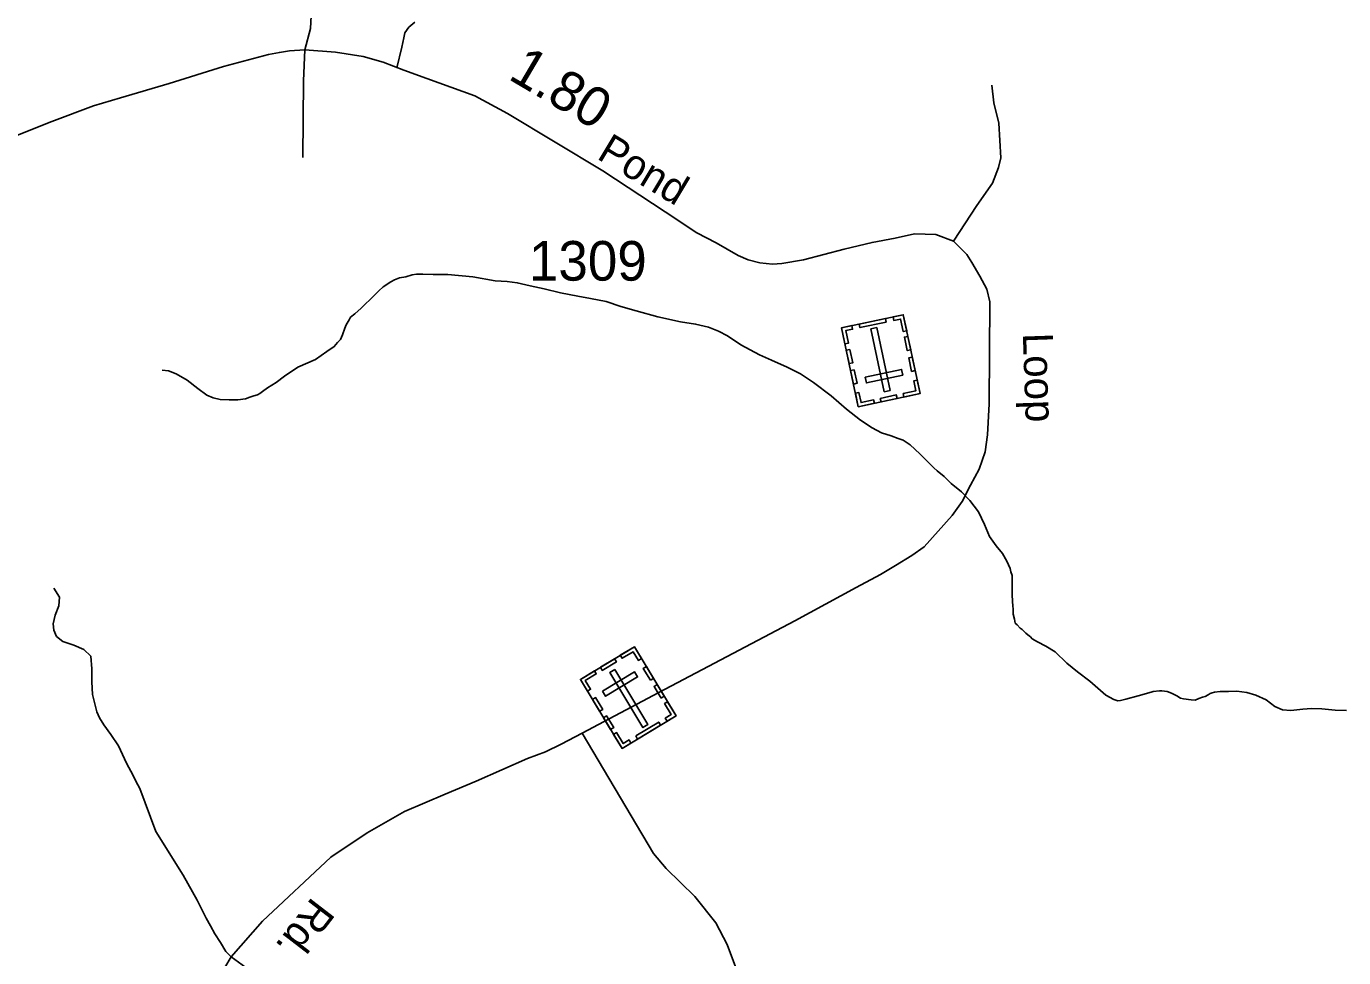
# Model space of a CAD drawing. Extents: x 2220236 to 2384410, y 720751 to 894131.
# Drawn here: x 2271918 to 2276076, y 823189 to 826128 of the extents above; entities that cross this region are included whole.
import ezdxf

# ---------------------------------------------------------------- set-up
doc = ezdxf.new("R2010")
doc.units = 0
doc.layers.add('Default', color=7, linetype='Continuous')

msp = doc.modelspace()

# ---------------------------------------------------------------- linework, layer by layer
at = {"layer": 'Default'}
for points in [[(2272668.9, 827422.7), (2272667.4, 827378.7), (2272658, 827302.7), (2272646.7, 827034.6), (2272645.9, 826910.7), (2272648.2, 826868.6), (2272658.5, 826824.8), (2272672.9, 826787), (2272695.4, 826743.3), (2272754.7, 826585.9), (2272783.6, 826504.1), (2272793.8, 826466.3), (2272804.4, 826416.3), (2272820.9, 826241.8), (2272815, 826121.7), (2272797.3, 826054.7)], [(2273144.6, 826141.4), (2273124.9, 826125.6), (2273113.1, 826107.9), (2273109.2, 826092.1), (2273103.3, 826062.6), (2273087.5, 825997.7)], [(2271512.3, 825634.5), (2271998.5, 825828.3), (2272130.4, 825877.6), (2272215, 825903.2), (2272369, 825948.5), (2272540.4, 826002.1), (2272682, 826039.3), (2272717.1, 826046.3), (2272749.1, 826050.8), (2272797.3, 826054.7), (2272893.9, 826047.3), (2272981.3, 826033.1), (2273044.2, 826015.4), (2273109.2, 825989.8), (2273182, 825964.2), (2273333.4, 825909.1), (2273436.7, 825853.9), (2273737.7, 825672.8), (2273934.1, 825543.3), (2274034.7, 825476.4), (2274094.9, 825445), (2274165.2, 825405.5), (2274196.2, 825391.3), (2274233.5, 825382.3), (2274272.9, 825377.5), (2274302.4, 825379.5), (2274371.3, 825391.3), (2274499.1, 825424.8), (2274587.7, 825446.4), (2274660.5, 825460.2), (2274721.5, 825474), (2274788.3, 825472), (2274844.6, 825450), (2274886.9, 825408.3), (2274902.5, 825383.4), (2274928, 825340.1), (2274949.7, 825298.8), (2274959.5, 825259.4), (2274957.3, 824937.3), (2274952.3, 824839.4), (2274944.6, 824785.3), (2274925.1, 824731.1), (2274897.8, 824680.9), (2274872.3, 824628.6), (2274840.8, 824584.4), (2274751.7, 824485.5), (2274712.6, 824458.2), (2274661.4, 824426.7), (2274614.6, 824398.2), (2274537, 824357.5), (2274344, 824251.7), (2273914.4, 824025.9), (2273672.7, 823898.1), (2273605.8, 823862.6), (2273556.6, 823839), (2273499.6, 823817.4), (2273338.2, 823746.5), (2273239.9, 823705.1), (2273112, 823650), (2272993.9, 823583.1), (2272879.7, 823506.3), (2272663.6, 823304.5), (2272564.9, 823191.5), (2272524.2, 823124.4)], [(2272797.3, 826054.7), (2272793.4, 825956.3), (2272790.4, 825714.2)], [(2274965.9, 825942.9), (2274972.3, 825887), (2274987.1, 825823.1), (2274994, 825713.2), (2274986.3, 825683.2), (2274967.4, 825633.4), (2274918.2, 825562.6), (2274844.6, 825450)], [(2274070.9, 825178.8), (2274030.7, 825188.8), (2273983, 825196.4), (2273910.8, 825211.6), (2273842.7, 825231.1), (2273794.8, 825244.5), (2273748.5, 825260.2), (2273698.5, 825269.5), (2273658.3, 825276.9), (2273604.1, 825286.9), (2273552.2, 825300.4), (2273508.1, 825309.5), (2273467.7, 825319.2), (2273435.9, 825323.1), (2273397.9, 825324.9), (2273327.7, 825337.8), (2273248.1, 825345.1), (2273201.9, 825345.4), (2273169.8, 825346.7), (2273149.7, 825346.4), (2273135.9, 825344.1), (2273115.8, 825338), (2273096, 825334.4), (2273080.2, 825328.2), (2273068.2, 825321.9), (2273044.3, 825306), (2273030.6, 825293.2), (2273006.4, 825269.1), (2272984.7, 825248.8), (2272975, 825239.2), (2272955.3, 825220.9), (2272941.3, 825210.4), (2272937.2, 825202.3), (2272927.3, 825186.1), (2272923.5, 825176.3), (2272915.8, 825154.5), (2272909.7, 825140.5), (2272899.9, 825130.2), (2272890.2, 825118), (2272866.2, 825102.1), (2272830.6, 825077.5), (2272775, 825053.1), (2272733.1, 825024.5), (2272707.1, 825004.7), (2272679.2, 824987.9), (2272663.5, 824976), (2272655.5, 824969.6), (2272647.6, 824965.6), (2272635.7, 824961.9), (2272623.5, 824957.9), (2272609.6, 824953.2), (2272585.9, 824949.8), (2272558, 824949.4), (2272529.8, 824950.9), (2272508, 824956.3), (2272487.5, 824964.9), (2272459.7, 824985.8), (2272425.5, 825012.1), (2272391.1, 825031.5), (2272367.1, 825041.2), (2272347.1, 825043.3)], [(2276084.9, 823968.8), (2276048.9, 823970.2), (2276007, 823974.3), (2275974.9, 823976), (2275947, 823973.9), (2275909.1, 823969.1), (2275883.3, 823971.3), (2275858.9, 823982.3), (2275831.1, 824002.6), (2275798.6, 824018), (2275770.6, 824026.1), (2275738.5, 824030.1), (2275712.6, 824029.6), (2275686.7, 824029.5), (2275668.6, 824027.2), (2275660.7, 824025.1), (2275654.7, 824022.6), (2275648.8, 824018.8), (2275638.8, 824013.1), (2275630.9, 824011), (2275619, 824006.9), (2275606.8, 824002.3), (2275595, 824002.5), (2275570.8, 824006.3), (2275561, 824008.1), (2275549, 824015.9), (2275532.8, 824023.5), (2275518.8, 824029.7), (2275502.4, 824031.7), (2275494.6, 824031.8), (2275474.5, 824029.6), (2275468.5, 824027.4), (2275427, 824015.2), (2275388.7, 824004.5), (2275371.2, 824000.6), (2275363, 824000.1), (2275351, 824004.3), (2275325, 824018), (2275274.8, 824061.6), (2275236.3, 824091.3), (2275202.1, 824118.9), (2275165.5, 824154.1), (2275135.7, 824172.1), (2275109.4, 824185.8), (2275093.2, 824195.9), (2275087.4, 824201.6), (2275079.3, 824207.7), (2275073.2, 824213.4), (2275061, 824225.1), (2275055.2, 824229.5), (2275045.2, 824239.6), (2275039.1, 824245.3), (2275037.1, 824257.8), (2275032.5, 824273.3), (2275032.5, 824291.3), (2275032.3, 824297.2), (2275030.1, 824333.4), (2275030, 824373.4), (2275029.6, 824387.5), (2275029.4, 824395.7), (2275025.4, 824407.3), (2275023.3, 824417.1), (2275013, 824441), (2274998.7, 824465.2), (2274978.9, 824488.6), (2274958.5, 824518.5), (2274942.3, 824556.6), (2274923.7, 824596.3), (2274895.6, 824632), (2274869.3, 824659.8), (2274837, 824685.7), (2274814.8, 824707.5), (2274792.6, 824725.3), (2274782.6, 824735.4), (2274738.6, 824778.9), (2274708, 824808.1), (2274685.7, 824822.6), (2274670.1, 824827.9), (2274647.9, 824835.6), (2274617.6, 824846), (2274587.8, 824861.4), (2274551.5, 824885.1), (2274507, 824920.5), (2274458.7, 824962.5), (2274402.5, 825004), (2274362, 825031.7), (2274319.8, 825053.3), (2274269.8, 825074.6), (2274231.8, 825091.8), (2274173.4, 825123.5), (2274131.3, 825151.3), (2274103.1, 825166.6), (2274070.9, 825178.8)], [(2272005.3, 824354.8), (2272023, 824327.2), (2272021.1, 824299.7), (2272009.2, 824270.1), (2272003.3, 824242.6), (2272005.3, 824222.9), (2272013.2, 824203.2), (2272032.9, 824187.5), (2272068.3, 824175.7), (2272099.7, 824161.9), (2272121.4, 824140.2), (2272125.3, 824100.8), (2272125.3, 824059.5), (2272127.3, 824020.1), (2272133.2, 823994.5), (2272141.1, 823965), (2272148.7, 823946.4), (2272162.7, 823923.7), (2272184.6, 823893.9), (2272209, 823857.2), (2272234.4, 823802.9), (2272255.4, 823764.4), (2272264.1, 823746), (2272276, 823722.6), (2272327.1, 823587.2), (2272412.6, 823449.2), (2272457.8, 823370.5), (2272485.4, 823313.4), (2272499.1, 823289.7), (2272512.9, 823264.2), (2272530.6, 823236.6), (2272548.3, 823209), (2272564.9, 823191.5)], [(2273672.7, 823898.1), (2273739.6, 823783.9), (2273898, 823518.1), (2273937.3, 823470.9), (2274027.8, 823382.3), (2274094.7, 823299.6), (2274130.1, 823230.7), (2274159.6, 823151.9), (2274187.2, 823081.1), (2274182.3, 823053.5), (2274164.6, 823022)], [(2274164.6, 823022), (2273845.4, 823069.6), (2273647.2, 823079.7), (2273589.3, 823081.3), (2273559.4, 823074.9), (2273517.4, 823068.6), (2273459.8, 823046), (2273390.3, 822991.5), (2273240.1, 822808), (2273220.3, 822789.8), (2273166.3, 822779.4), (2273136.3, 822779), (2273070.1, 822806.3), (2272975.6, 822865.5), (2272858.7, 822958.3), (2272768.2, 823037.6), (2272703.7, 823090.9), (2272564.9, 823191.5)]]:
    msp.add_lwpolyline(points, dxfattribs=at)
for points in [[(2274738.9, 824969.3), (2274544.1, 824927.9), (2274491.2, 825177), (2274686, 825218.3)], [(2274653.6, 825211.4), (2274656, 825200.2), (2274677.5, 825204.8), (2274685.9, 825165.2), (2274696.8, 825167.5), (2274686, 825218.3)], [(2274523.6, 825183.9), (2274526, 825172.6), (2274504.5, 825168.1), (2274512.9, 825128.5), (2274502, 825126.2), (2274491.2, 825177)], [(2274632.2, 825195.2), (2274549.2, 825177.6), (2274546.8, 825188.7), (2274629.8, 825206.3)], [(2274626.1, 824975.3), (2274644.4, 824979.2), (2274602.3, 825177.5), (2274584, 825173.6)], [(2274700.5, 825149.9), (2274709.5, 825107.6), (2274698.4, 825105.2), (2274689.4, 825147.6)], [(2274517.4, 825108.7), (2274526.4, 825066.3), (2274515.2, 825063.9), (2274506.2, 825106.3)], [(2274714.5, 825084.2), (2274723.5, 825041.8), (2274712.3, 825039.4), (2274703.4, 825081.8)], [(2274531, 825044.2), (2274540, 825001.8), (2274528.9, 824999.4), (2274519.9, 825041.8)], [(2274684.8, 825027.4), (2274680.9, 825045.6), (2274565.8, 825021.2), (2274569.6, 825002.9)], [(2274729.9, 825011.6), (2274718.8, 825009.3), (2274725.5, 824977.8), (2274685.8, 824969.4), (2274688.1, 824958.5), (2274738.9, 824969.3)], [(2274535, 824970.3), (2274546.1, 824972.7), (2274552.8, 824941.2), (2274592.5, 824949.6), (2274594.8, 824938.7), (2274544.1, 824927.9)], [(2274666.4, 824953.9), (2274615.7, 824943.1), (2274613.3, 824954.3), (2274664, 824965)], [(2273666.8, 824067.5), (2273837.3, 824170.3), (2273968.8, 823952.3), (2273798.3, 823849.4)], [(2273859.7, 824133.2), (2273850, 824127.3), (2273833.4, 824154.9), (2273798.7, 824134), (2273792.9, 824143.5), (2273837.4, 824170.3)], [(2273730.2, 824105.7), (2273774.6, 824132.5), (2273780.5, 824122.7), (2273736.1, 824095.9)], [(2273689.2, 824030.4), (2273698.9, 824036.2), (2273682.3, 824063.8), (2273717, 824084.7), (2273711.3, 824094.3), (2273666.8, 824067.5)], [(2273736.9, 824030.3), (2273746.6, 824014.3), (2273847.4, 824075.1), (2273837.7, 824091.1)], [(2273775.3, 824098.7), (2273759.3, 824089), (2273864.1, 823915.4), (2273880, 823925.1)], [(2273887.7, 824064.7), (2273865.3, 824101.8), (2273875.1, 824107.7), (2273897.5, 824070.6)], [(2273921.7, 824008.3), (2273899.4, 824045.4), (2273909.1, 824051.3), (2273931.5, 824014.2)], [(2273727.5, 823966.9), (2273705.1, 824004), (2273714.8, 824009.8), (2273737.2, 823972.7)], [(2273940.4, 823935.2), (2273934.5, 823945), (2273953.3, 823956.4), (2273932.5, 823991), (2273942, 823996.7), (2273968.8, 823952.3)], [(2273762.2, 823909.3), (2273739.8, 823946.4), (2273749.6, 823952.3), (2273771.9, 823915.2)], [(2273841.6, 823888.9), (2273914.3, 823932.8), (2273920.2, 823923), (2273847.5, 823879.2)], [(2273826.6, 823866.6), (2273820.7, 823876.4), (2273801.9, 823865), (2273781, 823899.6), (2273771.5, 823893.9), (2273798.3, 823849.5)]]:
    msp.add_lwpolyline(points, close=True, dxfattribs=at)

# ---------------------------------------------------------------- texts
for s, height, rotation, p in [('1.80', 125, 329.4508, (2273435.2, 825964.3)), ('Pond', 95, 329.071, (2273715.3, 825712.7)), ('Loop', 95, 271.9152, (2275063.2, 825159.8)), ('Rd.', 95, 232.4008, (2272821.2, 823383.8))]:
    msp.add_text(s, height=height, rotation=rotation, dxfattribs=at).set_placement(p)
msp.add_text('1309', height=125, dxfattribs=at).set_placement((2273504.5, 825325.9))

doc.saveas('drawing.dxf')
